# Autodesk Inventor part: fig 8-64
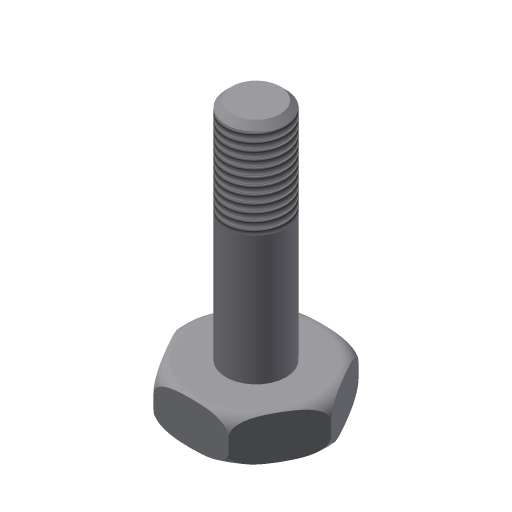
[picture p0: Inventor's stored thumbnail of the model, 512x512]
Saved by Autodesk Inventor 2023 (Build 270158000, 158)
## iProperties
Created: 2002-01
Part Number: fig 8-64
Document SubType Name: Modeling
Designer: ***
Density: 1 g/cm^3
Material: Generic
Appearance: Default
Control State: 0
Master: False
Checked Out: False
Shininess: 77.0
Length Units: 11269
Angle Units: 11279
Time Units: 11290
Mass Units: 11283
Length Display Precision: 3
Angle Display Precision: 2
Density: 0.0
Volumn: 0.0
Area: 0.0
PropertySet Name: Model Information
Author: ***
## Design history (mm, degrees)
sketch "Sketch1"
  geometry: C1 r 25 at (0, 0)
  constraints: 1 centre point
  dimensions: "d0" = 50 diameter of C1
extrude "Extrusion1" new body sketch "Sketch1" distance "d1" = 15; taper "d2" = 0 deg
fillet "Fillet1" dims "d3" = 5
sketch "Sketch2"
  geometry: L1 (25.058, 0)-(12.529, -21.701); L2 (12.529, -21.701)-(-12.529, -21.701); L3 (-12.529, -21.701)-(-25.058, 0); L4 (-25.058, 0)-(-12.529, 21.701); L5 (-12.529, 21.701)-(12.529, 21.701); L6 (12.529, 21.701)-(25.058, 0); 1 further point
  constraints: 12 end point, 11 other
extrude "Extrusion2" sketch "Sketch2" extent not by distance; stored distance "d4" = 15; taper "d5" = 0 deg
sketch "Sketch3"
  geometry: C1 r 10.044 at (0, 0); 1 further point
  constraints: 1 centre point, 1 coincident
extrude "Extrusion3" join sketch "Sketch3" distance "d6" = 75; taper "d7" = 0 deg
chamfer "Chamfer1" distance "d8" = 2; stored, may be unused: second distance "d9" = 2, angle "d16" = 45 deg
thread "Thread3" dims "d14" = 30, "d15" = 0
body "Solid1"
